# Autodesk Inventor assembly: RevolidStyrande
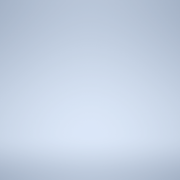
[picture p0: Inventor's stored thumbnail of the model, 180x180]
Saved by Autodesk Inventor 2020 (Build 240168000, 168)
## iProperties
Created: 2019-06
Part Number: RevolidStyrande
Document SubType Name: Assembly
Designer: cl
Daghöjd: 2500,000 mm
Dagbredd: 2000,000 mm
Author: cl
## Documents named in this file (1)
- G:\AutoCad\Carl Lund\Revolid\RevolidStyrande.iam
